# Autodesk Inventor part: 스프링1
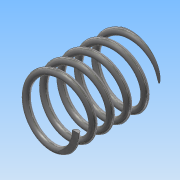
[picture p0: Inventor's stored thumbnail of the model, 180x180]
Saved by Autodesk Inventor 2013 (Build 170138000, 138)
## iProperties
Created: 2016-10
Part Number: 스프링1
Material: 강철, 탄소
Document SubType Name: Modeling
Designer: Administrator
Mass: 4.26122 g
Surface Area: 11.283 cm^2
Volume: 0.541451 cm^3
Density: 7.87 g/cm^3
Author: Administrator
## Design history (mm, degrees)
sketch "스케치1"
  geometry: L1 (0, 0)-(0, 16.67); L2 (0, 16.67)-(25, 16.67); C1 r 1 at (9, 0)
  constraints: 4 end point, 1 centre point, 1 horizontal alignment, 1 perpendicular, 1 vertical
  dimensions: "d0" = 16.66987 distance of L1.start L1.end (derived); "d1" = 25 distance of L1.end L2.end; "d2" = 2 diameter of C1; "d3" = 18 diameter of C1.centre L1
feature "코일1" sketch "스케치1" pitch "d4" = 10; turns "d6" = 5; dims "d5" = 27, "d7" = 0, angle "d8" = 90 deg, angle "d9" = 90 deg, "d10" = 0, "d11" = 0
sketch "스케치2"
  geometry: L1 (16.67, 12)-(0, 12); L2 (0, 12)-(0, -12); L3 (0, -12)-(16.67, -12); L4 (16.67, -12)-(16.67, 12); 2 further points
  constraints: 8 end point, 2 parallel, 1 coincident, 1 horizontal, 1 midpoint, 1 perpendicular
  dimensions: "d12" = 16.66987 distance of L1.start L1.end (derived); "d14" = 24 distance of L3.end L1.start
extrude "돌출1" sketch "스케치2" stored distance "d15" = 0; taper "d16" = 0 deg
node "솔리드1"
